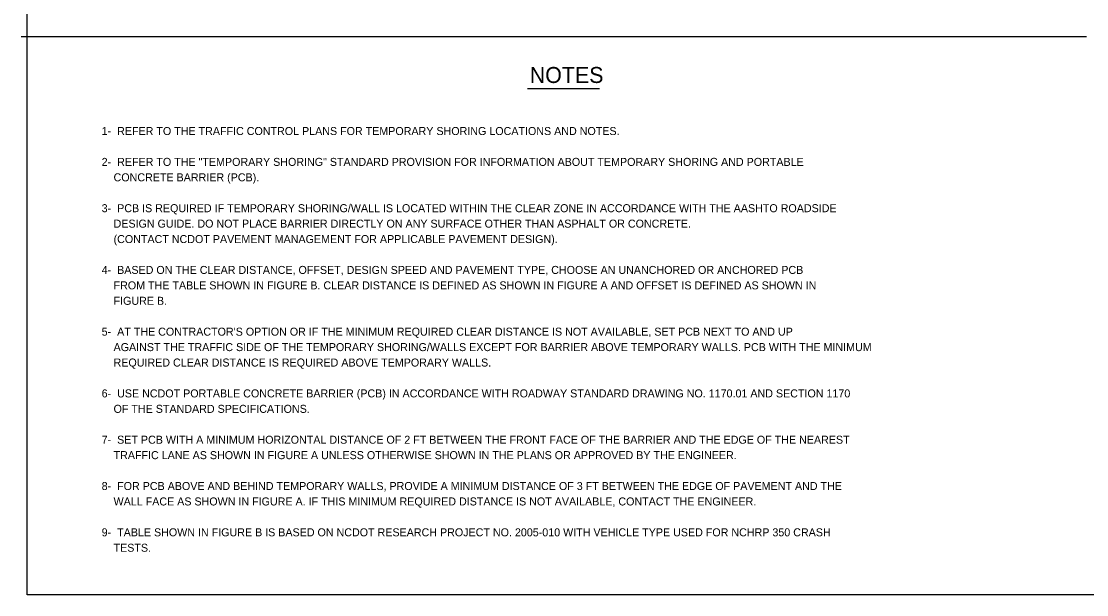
# Model space of a CAD drawing. Extents: x 2487012 to 2497594, y 369516 to 371986.
# Drawn here: x 2487012 to 2487943, y 370218 to 370720 of the extents above; entities that cross this region are included whole.
import ezdxf

# ---------------------------------------------------------------- set-up
doc = ezdxf.new("R2010")
doc.units = 0
for name, color, linetype in [('TC SHEET BORDER LINE THIN', 7, 'Continuous'), ('TC SHEET LAYOUT SHAPE', 7, 'Continuous'), ('TC SHEET TEXT', 7, 'Continuous')]:
    doc.layers.add(name, color=color, linetype=linetype)

msp = doc.modelspace()

# ---------------------------------------------------------------- linework, layer by layer
at = {"layer": 'TC SHEET BORDER LINE THIN'}
msp.add_line((2487011.56, 370706.61), (2487943.32, 370706.61), dxfattribs=at)
at = {"layer": 'TC SHEET LAYOUT SHAPE'}
msp.add_lwpolyline([(2487016.56, 370666.84), (2487016.56, 370976.16), (2487016.56, 371248.27), (2487026.56, 371258.27), (2487469.58, 371258.27), (2487940.56, 371258.27), (2488261.56, 371258.27), (2488261.56, 371178.27), (2488346.56, 371178.27), (2488346.56, 371226.27), (2488506.56, 371226.27), (2488506.56, 370891.3), (2488506.56, 370612.1), (2488506.56, 370360.77), (2488151.56, 370360.77), (2488151.56, 370218.27), (2487778.38, 370218.27), (2487608.92, 370218.27), (2487256.14, 370218.27), (2487016.56, 370218.27)], close=True, dxfattribs=at)
at = {"layer": 'TC SHEET TEXT'}
msp.add_line((2487454.28, 370661.1), (2487517.44, 370661.1), dxfattribs=at)

# ---------------------------------------------------------------- texts
for s, height, p in [('NOTES', 14, (2487456.31, 370665.85)), ('1-  REFER TO THE TRAFFIC CONTROL PLANS FOR TEMPORARY SHORING LOCATIONS AND NOTES.', 7, (2487081.86, 370620.33)), ('2-  REFER TO THE "TEMPORARY SHORING" STANDARD PROVISION FOR INFORMATION ABOUT TEMPORARY SHORING AND PORTABLE', 7, (2487081.86, 370593.33)), ('    CONCRETE BARRIER (PCB). ', 7, (2487081.86, 370579.83)), ('3-  PCB IS REQUIRED IF TEMPORARY SHORING/WALL IS LOCATED WITHIN THE CLEAR ZONE IN ACCORDANCE WITH THE AASHTO ROADSIDE ', 7, (2487081.86, 370552.83)), ('    DESIGN GUIDE. DO NOT PLACE BARRIER DIRECTLY ON ANY SURFACE OTHER THAN ASPHALT OR CONCRETE. ', 7, (2487081.86, 370539.33)), ('    (CONTACT NCDOT PAVEMENT MANAGEMENT FOR APPLICABLE PAVEMENT DESIGN). ', 7, (2487081.86, 370525.83)), ('4-  BASED ON THE CLEAR DISTANCE, OFFSET, DESIGN SPEED AND PAVEMENT TYPE, CHOOSE AN UNANCHORED OR ANCHORED PCB ', 7, (2487081.86, 370498.83)), ('    FROM THE TABLE SHOWN IN FIGURE B. CLEAR DISTANCE IS DEFINED AS SHOWN IN FIGURE A AND OFFSET IS DEFINED AS SHOWN IN ', 7, (2487081.86, 370485.33)), ('    FIGURE B.', 7, (2487081.86, 370471.83)), ("5-  AT THE CONTRACTOR'S OPTION OR IF THE MINIMUM REQUIRED CLEAR DISTANCE IS NOT AVAILABLE, SET PCB NEXT TO AND UP ", 7, (2487081.86, 370444.83)), ('    AGAINST THE TRAFFIC SIDE OF THE TEMPORARY SHORING/WALLS EXCEPT FOR BARRIER ABOVE TEMPORARY WALLS. PCB WITH THE MINIMUM ', 7, (2487081.86, 370431.33)), ('    REQUIRED CLEAR DISTANCE IS REQUIRED ABOVE TEMPORARY WALLS. ', 7, (2487081.86, 370417.83)), ('6-  USE NCDOT PORTABLE CONCRETE BARRIER (PCB) IN ACCORDANCE WITH ROADWAY STANDARD DRAWING NO. 1170.01 AND SECTION 1170 ', 7, (2487081.86, 370390.83)), ('    OF THE STANDARD SPECIFICATIONS.  ', 7, (2487081.86, 370377.33)), ('7-  SET PCB WITH A MINIMUM HORIZONTAL DISTANCE OF 2 FT BETWEEN THE FRONT FACE OF THE BARRIER AND THE EDGE OF THE NEAREST ', 7, (2487081.86, 370350.33)), ('    TRAFFIC LANE AS SHOWN IN FIGURE A UNLESS OTHERWISE SHOWN IN THE PLANS OR APPROVED BY THE ENGINEER.', 7, (2487081.86, 370336.83)), ('8-  FOR PCB ABOVE AND BEHIND TEMPORARY WALLS, PROVIDE A MINIMUM DISTANCE OF 3 FT BETWEEN THE EDGE OF PAVEMENT AND THE ', 7, (2487081.86, 370309.83)), ('    WALL FACE AS SHOWN IN FIGURE A. IF THIS MINIMUM REQUIRED DISTANCE IS NOT AVAILABLE, CONTACT THE ENGINEER.', 7, (2487081.86, 370296.33)), ('9-  TABLE SHOWN IN FIGURE B IS BASED ON NCDOT RESEARCH PROJECT NO. 2005-010 WITH VEHICLE TYPE USED FOR NCHRP 350 CRASH ', 7, (2487081.86, 370269.33)), ('    TESTS.  ', 7, (2487081.86, 370255.83))]:
    msp.add_text(s, height=height, dxfattribs=at).set_placement(p)

doc.saveas('drawing.dxf')
